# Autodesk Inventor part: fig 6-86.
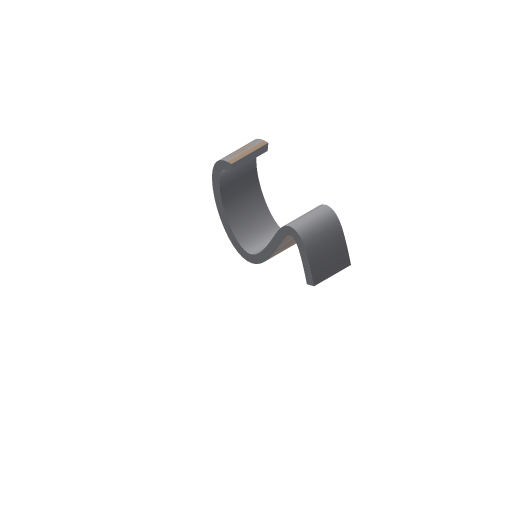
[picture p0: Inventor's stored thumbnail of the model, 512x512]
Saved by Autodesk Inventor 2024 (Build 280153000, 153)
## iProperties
Shininess: 64.0
Length Units: 11269
Angle Units: 11279
Time Units: 11290
Mass Units: 11283
Length Display Precision: 3
Angle Display Precision: 2
Compacted: True
Part Number: fig 6-86.
Document SubType Name: Modeling
Created: 2002-12
Designer: deepak
Density: 1 g/cm^3
Material: Generic
Appearance: Default
Density: 0.0
Volumn: 0.0
Area: 0.0
PropertySet Name: Model Information
Control State: 0
Master: False
Checked Out: False
Author: deepak
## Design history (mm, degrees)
sketch "Sketch1"
  geometry: 5 further points
  constraints: 5 other
extrude_surface "ExtrusionSrf1" sketch "Sketch1" dims "d0" = 20, "d1" = 0
thicken "Thicken2" dims "d6" = 4, "d7" = 4
body "Solid1"
body "Srf1"
